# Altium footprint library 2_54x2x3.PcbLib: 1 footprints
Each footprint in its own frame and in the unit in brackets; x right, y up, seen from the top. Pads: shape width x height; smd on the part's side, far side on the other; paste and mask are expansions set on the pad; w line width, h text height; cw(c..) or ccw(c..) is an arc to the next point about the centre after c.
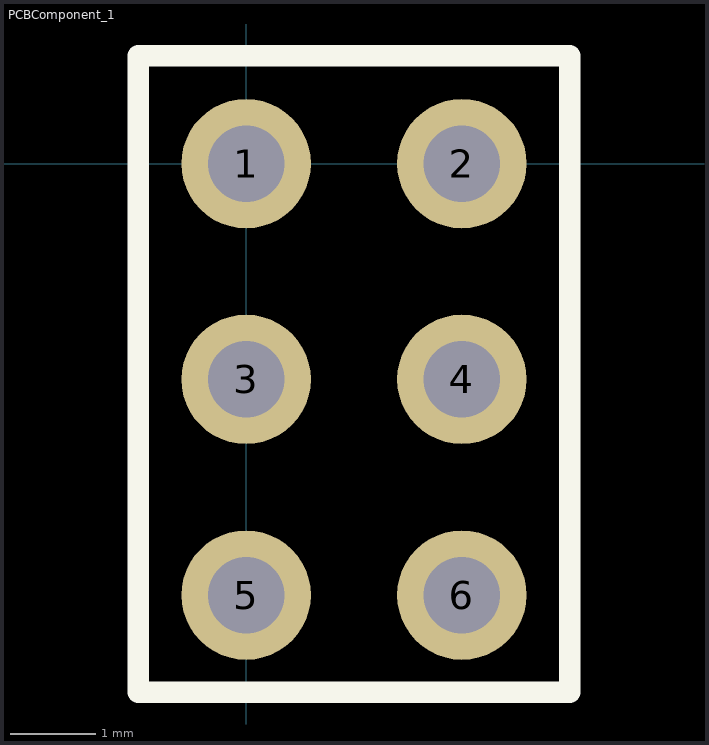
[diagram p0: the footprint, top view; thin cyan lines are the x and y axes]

## PCBComponent_1 [mil]
pads (6):
  round 60 hole 35.43: 1(0,0) 2(100,0) 3(0,-100) 4(100,-100) 5(0,-200) 6(100,-200)
Top Overlay:
  lines w10: -50,-245 150,-245 150,50 -50,50 -50,-245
